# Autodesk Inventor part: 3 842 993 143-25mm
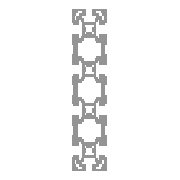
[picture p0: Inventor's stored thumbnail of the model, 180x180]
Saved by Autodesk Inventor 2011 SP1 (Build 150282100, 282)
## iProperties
Category: End -/-
Created: 2011-02
Part Number: 3 842 993 143-25mm
Document SubType Name: Modeling
Designer: SRW
Density: 2.71 g/cm^3
Categories: <MemberInstance><Categories><Category DisplayName="Structural Shapes" InternalName="089c4875-fa83-4c05-b084-43b9cc11f5ed" Mnemonic="GRDR"><CategoryParameter Dis
Stock Number: 3 842 993 143
Description: PROFILE 40x160, -/-
Material: Aluminum-6061
Mass: 136.52 g
Surface Area: 406.001 cm^2
Volume: 50.3762 cm^3
G_L: 25.000 mm
Author: SRW
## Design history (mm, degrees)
node "Blocks"
  sketch "40x160"
    geometry: L1 (119.264, -13.483)-(120.18, -13.084); L2 (117.078, -20.982)-(120.18, -20.982); L3 (120.18, -20.982)-(120.18, -17.879); L4 (120.18, -17.879)-(119.264, -17.48); L5 (120.18, -13.084)-(120.18, -9.982); L6 (116.679, -20.065)-(117.078, -20.982); L7 (117.078, -9.982)-(116.679, -10.898); L8 (120.859, -23.782)-(108.502, -23.782); L9 (112.682, -10.898)-(112.282, -9.982); L10 (112.282, -20.982)-(112.682, -20.065); L11 (109.18, -20.982)-(112.282, -20.982); L12 (109.18, -17.879)-(109.18, -20.982); L13 (110.097, -17.48)-(109.18, -17.879); L14 (112.282, -9.982)-(109.18, -9.982); L15 (109.18, -9.982)-(109.18, -13.084); L16 (109.18, -13.084)-(110.097, -13.483); L17 (94.68, -29.482)-(95.68, -29.482); L18 (94.68, -21.282)-(94.68, -29.482); L19 (107.18, 70.604)-(107.18, 58.433); L20 (107.18, 58.433)-(103.216, 54.468); L21 (108.502, 56.218)-(104.252, 51.968); L22 (100.68, 54.468)-(100.68, 59.518); L23 (103.216, 54.468)-(100.68, 54.468); L24 (104.252, 51.968)-(98.68, 51.968); L25 (94.68, 58.718)-(94.68, 50.518); L26 (100.68, 59.518)-(96.18, 59.518); L27 (96.18, 59.518)-(96.18, 58.718); L28 (96.18, 58.718)-(94.68, 58.718); L29 (112.282, 70.018)-(109.18, 70.018); L30 (122.18, -49.396)-(126.145, -45.432); L31 (122.18, -61.567)-(122.18, -49.396); L32 (112.282, -49.982)-(109.18, -49.982); L33 (120.18, -57.879)-(119.264, -57.48); L34 (95.68, -29.482)-(95.68, -41.482); L35 (98.68, -28.032)-(98.68, -42.932); L36 (104.252, -28.032)-(98.68, -28.032); L37 (117.078, -49.982)-(116.679, -50.898); L38 (108.502, -47.182)-(120.859, -47.182); L39 (119.264, -53.483)-(120.18, -53.084); L40 (120.18, -53.084)-(120.18, -49.982); L41 (120.18, -49.982)-(117.078, -49.982); L42 (120.859, -47.182)-(125.109, -42.932); L43 (130.68, -42.932)-(130.68, -28.032); L44 (130.68, -28.032)-(125.109, -28.032); L45 (125.109, -42.932)-(130.68, -42.932); L46 (112.682, -50.898)-(112.282, -49.982); L47 (96.18, -61.282)-(94.68, -61.282); L48 (96.18, -60.482)-(96.18, -61.282); L49 (109.18, -53.084)-(110.097, -53.483); L50 (109.18, -49.982)-(109.18, -53.084); L51 (104.252, -42.932)-(108.502, -47.182); L52 (110.097, -57.48)-(109.18, -57.879); L53 (100.68, -45.432)-(103.216, -45.432); L54 (100.68, -50.482)-(100.68, -45.432); L55 (98.68, -42.932)-(104.252, -42.932); L56 (107.18, -49.396)-(107.18, -61.567); L57 (94.68, -41.482)-(94.68, -49.682); L58 (95.68, -41.482)-(94.68, -41.482); L59 (96.18, -50.482)-(100.68, -50.482); L60 (96.18, -49.682)-(96.18, -50.482); L61 (100.68, -60.482)-(96.18, -60.482); L62 (94.68, -49.682)-(96.18, -49.682); L63 (103.216, -45.432)-(107.18, -49.396); L64 (108.88, -73.982)-(109.68, -73.982)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; A1 r 5 centre (114.68, -15.482) between (119.264, -17.48) and (119.264, -13.483); A2 r 5 centre (114.68, -15.482) between (116.679, -10.898) and (112.682, -10.898); A3 r 5 centre (114.68, -15.482) between (112.682, -20.065) and (116.679, -20.065); A4 r 5 centre (114.68, -15.482) between (110.097, -13.483) and (110.097, -17.48); A5 r 5 centre (114.68, -55.482) between (119.264, -57.48) and (119.264, -53.483); A6 r 5 centre (114.68, -55.482) between (116.679, -50.898) and (112.682, -50.898); A7 r 5 centre (114.68, -55.482) between (110.097, -53.483) and (110.097, -57.48); A8 r 1.5 centre (105.18, -72.482) between (105.18, -73.982) and (105.18, -70.982); A9 r 2.75 centre (100.18, -69.982) between (102.93, -69.982) and (100.18, -67.232); A10 r 0.5 centre (99.68, -73.193) between (100.18, -73.193) and (99.757, -72.699); A11 r 2.75 centre (100.18, -69.982) between (97.463, -70.405) and (99.757, -72.699); A12 r 0.5 centre (96.969, -70.482) between (97.463, -70.405) and (96.969, -69.982); A13 r 3 centre (97.68, -72.482) between (94.68, -72.482) and (97.68, -75.482); A14 r 1.5 centre (97.68, -64.982) between (99.18, -64.982) and (96.18, -64.982); A15 r 3 centre (131.68, 81.518) between (134.68, 81.518) and (131.68, 84.518); A16 r 1.5 centre (131.68, 74.018) between (130.18, 74.018) and (133.18, 74.018); A17 r 1.5 centre (124.18, 81.518) between (124.18, 83.018) and (124.18, 80.018); A18 r 2.75 centre (129.18, 79.018) between (126.43, 79.018) and (129.18, 76.268); A19 r 0.5 centre (132.392, 79.518) between (131.898, 79.442) and (132.392, 79.018); A20 r 0.5 centre (129.68, 82.23) between (129.18, 82.23) and (129.603, 81.736); A21 r 2.75 centre (129.18, 79.018) between (131.898, 79.442) and (129.603, 81.736); A22 r 0.5 centre (132.392, -70.482) between (132.392, -69.982) and (131.898, -70.405); A23 r 3 centre (131.68, -72.482) between (131.68, -75.482) and (134.68, -72.482); A24 r 1.5 centre (131.68, -64.982) between (133.18, -64.982) and (130.18, -64.982); A25 r 2.75 centre (129.18, -69.982) between (129.603, -72.699) and (131.898, -70.405); A26 r 0.5 centre (129.68, -73.193) between (129.603, -72.699) and (129.18, -73.193); A27 r 2.75 centre (129.18, -69.982) between (129.18, -67.232) and (126.43, -69.982); A28 r 1.5 centre (124.18, -72.482) between (124.18, -70.982) and (124.18, -73.982); A29 r 5 centre (114.68, -55.482) between (112.682, -60.065) and (116.679, -60.065); A30 r 0.5 centre (99.68, 82.23) between (99.757, 81.736) and (100.18, 82.23); A31 r 3 centre (97.68, 81.518) between (97.68, 84.518) and (94.68, 81.518); A32 r 1.5 centre (105.18, 81.518) between (105.18, 80.018) and (105.18, 83.018); A33 r 2.75 centre (100.18, 79.018) between (99.757, 81.736) and (97.463, 79.442); A34 r 0.5 centre (96.969, 79.518) between (96.969, 79.018) and (97.463, 79.442); A35 r 2.75 centre (100.18, 79.018) between (100.18, 76.268) and (102.93, 79.018); A36 r 1.5 centre (97.68, 74.018) between (96.18, 74.018) and (99.18, 74.018); A37 r 5 centre (114.68, 64.518) between (110.097, 66.517) and (110.097, 62.52); A38 r 5 centre (114.68, 64.518) between (116.679, 69.102) and (112.682, 69.102); A39 r 5 centre (114.68, 64.518) between (112.682, 59.935) and (116.679, 59.935); A40 r 5 centre (114.68, 64.518) between (119.264, 62.52) and (119.264, 66.517); A41 r 5 centre (114.68, 24.518) between (112.682, 19.935) and (116.679, 19.935); A42 r 5 centre (114.68, 24.518) between (110.097, 26.517) and (110.097, 22.52); A43 r 5 centre (114.68, 24.518) between (119.264, 22.52) and (119.264, 26.517); A44 r 5 centre (114.68, 24.518) between (116.679, 29.102) and (112.682, 29.102); 1 further point
    constraints: 608 end point, 88 point on circle, 44 centre point, 1 coincident
node "Start Plane"
node "End Plane"
sketch "Sketch1"
  geometry: 1 further point
  constraints: 1 other
extrude "Body" new body sketch "Sketch1" stored distance "d4" = 0.13; taper "d5" = 0 deg
node "Driven Length"
  sketch "Sketch59"
    geometry: L1 (0, 0)-(10, 0) reference
    constraints: 2 end point, 1 horizontal
  workplane "Work Plane26"
  sketch "Sketch60"
    geometry: L1 (-28, 0)-(28, 0) reference; L2 (-28, 25)-(28, 25) reference
    dimensions: "d7" = 25 distance between parallel lines of L1 L2 (derived)
sketch "Sketch9"
  geometry: 4 further points
  constraints: 3 vertical alignment
  dimensions: "d88" = 40 distance of point (0, 0) point (0, -40); "d100" = 40 distance of point (0, -80) point (0, -40) (= d88); "d110" = 40 distance of point (0, -80) point (0, -120) (= d88)
hole "M12/-" sketch "Sketch9" at (0, 0), (0, -40), (0, -80), (0, -120) diameter "d17" = 10.106; stored, may be unused: countersink angle "d21" = 90 deg, drill point angle "d23" = 118 deg; dims "d18" = 6, "d19" = 4, "d20" = 2, "d22" = 55
sketch "Sketch10"
  geometry: 4 further points
  constraints: 3 vertical alignment
  dimensions: "d89" = 40 distance of point (0, 0) point (0, -40); "d101" = 40 distance of point (0, -40) point (0, -80) (= d89); "d111" = 40 distance of point (0, -80) point (0, -120) (= d89)
hole "-/M12" sketch "Sketch10" at (0, 0), (0, -40), (0, -80), (0, -120) diameter "d24" = 10.106; stored, may be unused: countersink angle "d28" = 90 deg, drill point angle "d30" = 118 deg; dims "d25" = 6, "d26" = 4, "d27" = 2, "d29" = 55
sketch "Sketch11"
  geometry: L1 (-13.7, 0)-(12.2, 0) reference; C1 r 8.5 at (0, 20); 1 further point
  constraints: 1 centre point, 1 vertical alignment
  dimensions: "d31" = 20 distance from line of C1.centre L1; "d32" = 17 diameter of C1
extrude "D17VS/-" cut sketch "Sketch11" stored distance "d33" = 10; taper "d34" = 0 deg
sketch "Sketch12"
  geometry: L1 (-13.7, 25)-(12.2, 25) reference; C1 r 8.5 at (0, 5); 1 further point
  constraints: 1 centre point, 1 vertical alignment
  dimensions: "d35" = 17 diameter of C1; "d36" = 20 distance from line of L1 C1.centre
extrude "-/D17VS" cut sketch "Sketch12" stored distance "d37" = 10; taper "d38" = 0 deg
sketch "Sketch13"
  geometry: L1 (-12.98, 0)-(7.88, 0) reference; C1 r 4.9 at (0, 20); 1 further point
  constraints: 1 centre point, 1 vertical alignment
  dimensions: "d39" = 9.8 diameter of C1; "d40" = 20 distance from line of C1.centre L1
extrude "D9.8VS/-" cut sketch "Sketch13" stored distance "d41" = 10; taper "d42" = 0 deg
sketch "Sketch14"
  geometry: L1 (-12.98, 25)-(7.88, 25) reference; C1 r 4.9 at (0, 5); 1 further point
  constraints: 1 centre point, 1 vertical alignment
  dimensions: "d43" = 9.8 diameter of C1; "d44" = 20 distance from line of L1 C1.centre
extrude "-/D9.8VS" cut sketch "Sketch14" stored distance "d45" = 10; taper "d46" = 0 deg
sketch "Sketch15"
  geometry: L1 (-150.86, 25)-(30.86, 25) reference; C1 r 4.9 at (0, 5); C2 r 4.9 at (-40, 5); C3 r 4.9 at (-80, 5); C4 r 4.9 at (-120, 5); 1 further point
  constraints: 4 centre point, 3 equal radius, 3 horizontal alignment, 1 vertical alignment
  dimensions: "d47" = 9.8 diameter of C1; "d48" = 20 distance from line of L1 C1.centre; "d92" = 40 distance of C1.centre C2.centre; "d102" = 40 distance of C2.centre C3.centre (= d92); "d115" = 40 distance of C3.centre C4.centre (= d92)
extrude "-/D9.8" cut sketch "Sketch15" stored distance "d49" = 10; taper "d50" = 0 deg
sketch "Sketch26"
  geometry: L1 (-150.86, 0)-(30.86, 0) reference; C1 r 4.9 at (0, 20); C2 r 4.9 at (-40, 20); C3 r 4.9 at (-80, 20); C4 r 4.9 at (-120, 20); 1 further point
  constraints: 4 centre point, 3 equal radius, 3 horizontal alignment, 1 vertical alignment
  dimensions: "d62" = 9.8 diameter of C1; "d65" = 20 distance from line of L1 C1.centre; "d93" = 40 distance of C1.centre C2.centre; "d103" = 40 distance of C2.centre C3.centre (= d93); "d114" = 40 distance of C4.centre C3.centre (= d93)
extrude "D9.8/-" cut sketch "Sketch26" stored distance "d63" = 10; taper "d64" = 0 deg
sketch "Sketch37"
  geometry: L1 (-155.9, 0)-(35.9, 0) reference; L2 (-155.9, 25)-(35.9, 25) reference; C1 r 8.5 at (0, 20); C2 r 8.5 at (-40, 20); C3 r 8.5 at (-80, 20); C4 r 8.5 at (-120, 20); 1 further point
  constraints: 4 centre point, 3 equal radius, 3 horizontal alignment, 1 vertical alignment
  dimensions: "d76" = 20 distance from line of C1.centre L1; "d77" = 17 diameter of C1; "d90" = 40 distance of C1.centre C2.centre; "d104" = 40 distance of C2.centre C3.centre (= d90); "d112" = 40 distance of C3.centre C4.centre (= d90)
extrude "D17/-" cut sketch "Sketch37" stored distance "d78" = 10; taper "d79" = 0 deg
sketch "Sketch38"
  geometry: L1 (-155.9, 25)-(35.9, 25) reference; C1 r 8.5 at (0, 5); C2 r 8.5 at (-40, 5); C3 r 8.5 at (-80, 5); C4 r 8.5 at (-120, 5); 1 further point
  constraints: 4 centre point, 3 equal radius, 3 horizontal alignment, 1 vertical alignment
  dimensions: "d80" = 17 diameter of C1; "d81" = 20 distance from line of L1 C1.centre; "d91" = 40 distance of C1.centre C2.centre; "d105" = 40 distance of C2.centre C3.centre (= d91); "d113" = 40 distance of C3.centre C4.centre (= d91)
extrude "-/D17" cut sketch "Sketch38" stored distance "d82" = 10; taper "d83" = 0 deg
body "Solid1"
node "40x160:1"
other parameters: "Length" = 25, "G_OFFSET_START" = 0 [user parameter; used in 2 equation terms], "G_OFFSET_END" = 0 [user parameter; used in 2 equation terms], "d2" = 0 (computed from G_OFFSET_START), "d3" = 25 (= Length + G_OFFSET_END), "G_L" = 25 (= d7) [user parameter], "Length2" = 25 (= G_OFFSET_START + Length + G_OFFSET_END) [user parameter], "d122" = 90 deg
